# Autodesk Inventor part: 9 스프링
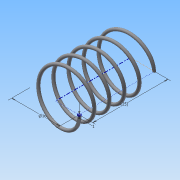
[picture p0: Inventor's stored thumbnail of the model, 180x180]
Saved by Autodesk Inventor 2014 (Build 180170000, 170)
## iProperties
Created: 2015-06
Part Number: 9 스프링
Material: 강철, 연강
Document SubType Name: Modeling
Designer: Administrator
Density: 7.86 g/cm^3
Appearance: 강철
Mass: 1.5292 g
Surface Area: 7.8715 cm^2
Volume: 0.194555 cm^3
Author: Administrator
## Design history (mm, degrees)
sketch "스케치1"
  geometry: L1 (0, 0)-(8, 0); L2 (8, 0)-(8, 14.5); L3 (8, 14.5)-(0, 14.5); L4 (0, 14.5)-(0, 0); C1 r 0.5 at (8, 0)
  constraints: 8 end point, 2 parallel, 1 centre point, 1 coincident, 1 horizontal, 1 perpendicular
  dimensions: "d0" = 16 diameter of L2 L4; "d1" = 14.5 distance of L1.end L2.end (derived); "d2" = 1 diameter of C1
feature "코일1" sketch "스케치1" pitch "d3" = 10; turns "d5" = 5; dims "d4" = 14.5 (= d1), "d6" = 0, angle "d7" = 90 deg, angle "d8" = 90 deg, "d9" = 0, "d10" = 0
sketch "스케치2"
  geometry: L1 (-8.5, 0)-(-7.5, 0) reference; 1 further point
  constraints: 1 horizontal alignment
extrude "돌출1" cut sketch "스케치2" stored distance "d11" = 10; taper "d12" = 0 deg
node "작업 평면1"
sketch "스케치3"
  geometry: L1 (8.5, 0)-(7.5, 0) reference; 1 further point
  constraints: 1 horizontal alignment
extrude "돌출2" cut sketch "스케치3" stored distance "d14" = 10; taper "d15" = 0 deg
node "솔리드1"
node "절단 모서리 투영1"
node "절단 모서리 투영2"
other parameters: "d13" = -14.5 (= -d1)
